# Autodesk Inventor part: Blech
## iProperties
Created: 2009-02
Part Number: Blech
Project: 1.4301
Material: Edelstahl
Document SubType Name: Blech
Designer: dr
Engineer: Blech 3 mm
Mass: 258.703 g
Surface Area: 227.926 cm^2
Volume: 32.0176 cm^3
Density: 8.08 g/cm^3
Cost Center: 0,26 kg
Checked By: dr
Description: Einlaufgeländer
Authority: 32017 mm^3
Flat Pattern Width: 1.02898 cm
Flat Pattern Length: 6.01083 cm
Flat Pattern Area: 6.18502 cm^2
Author: dr
Revision Number: 02-3530
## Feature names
1. Extrusion1
2. Erhebung1
3. Extrusion2
4. Bohrung2 [Hole]
5. Bohrung3 [Hole]
6. Bohrung4 [Hole]
